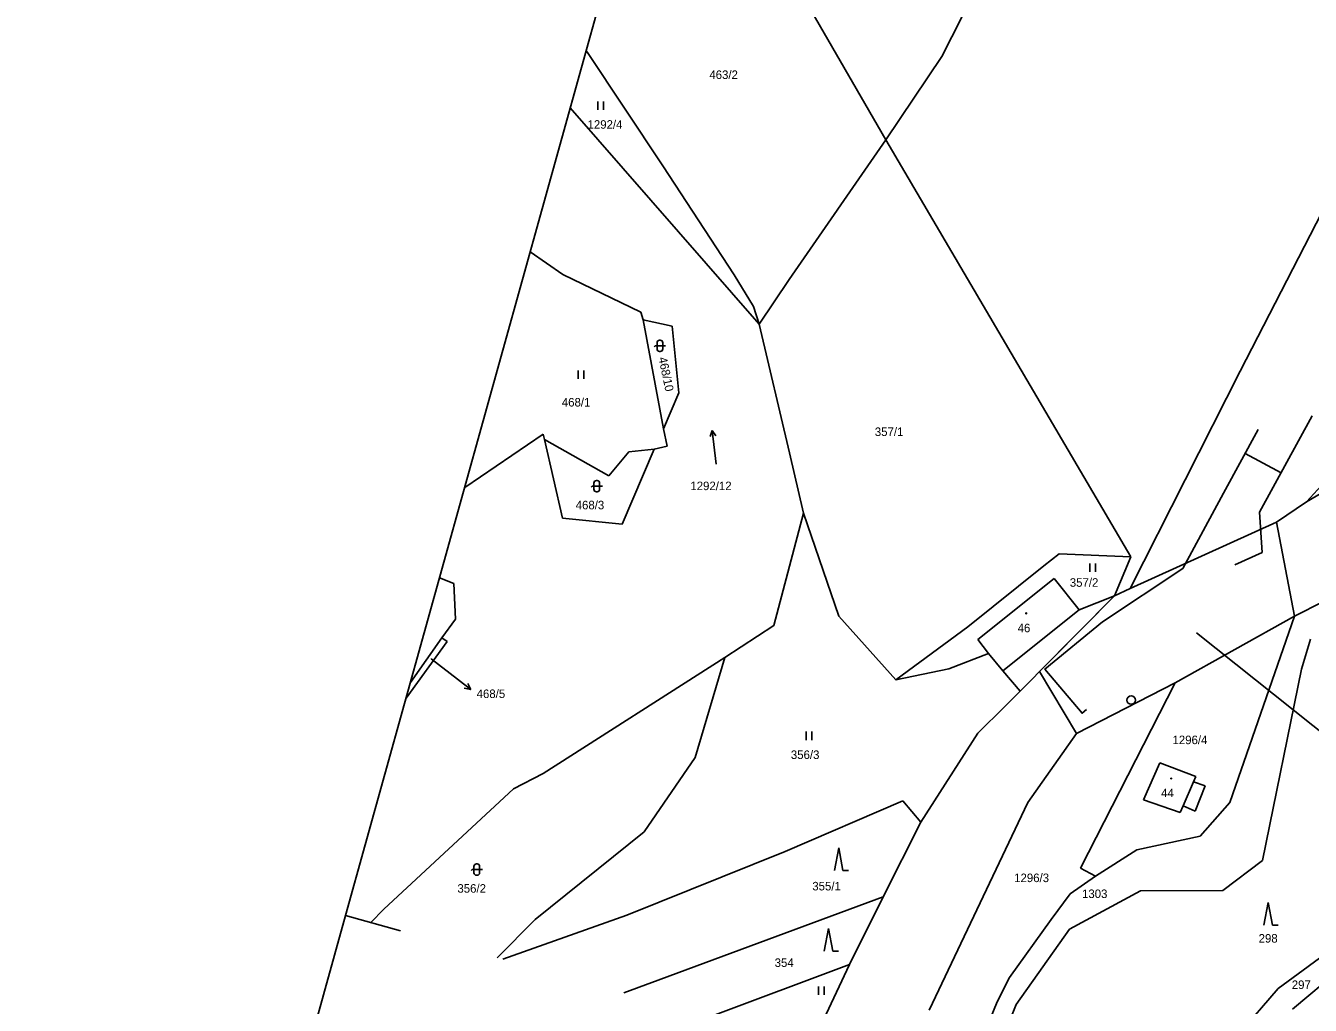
# Model space of a CAD drawing. Extents: x -795094 to -794639, y -1135368 to -1134681.
# Drawn here: x -795094.1 to -794868.2, y -1135101.6 to -1134929.4 of the extents above; entities that cross this region are included whole.
import ezdxf

# ---------------------------------------------------------------- set-up
doc = ezdxf.new("R2010")
doc.units = 0
for name, color, linetype in [('Default', 7, 'Continuous'), ('formát', 7, 'Continuous'), ('kilometráž - vrstava 7', 7, 'Continuous'), ('kn_celek - Cisla parcel pomocna', 7, 'Continuous'), ('kn_celek - Cisla pozemkovych parcel', 7, 'Continuous'), ('kn_celek - Cisla stavebnich parcel', 7, 'Continuous'), ('kn_celek - Hranice parcel', 7, 'Continuous'), ('kn_celek - Vnitrni kresby', 7, 'Continuous'), ('kn_celek - Znacky budov', 7, 'Continuous'), ('kn_celek - Znacky kultur', 7, 'Continuous'), ('plochy - SZDC', 7, 'Continuous'), ('plochy - TZ_ostat', 7, 'Continuous'), ('PSR_C2_1_trasa_Strunkovice - Kabelová trasa', 7, 'Continuous'), ('SOPS', 7, 'Continuous')]:
    doc.layers.add(name, color=color, linetype=linetype)

# ---------------------------------------------------------------- blocks, each defined once
blk = doc.blocks.new('308')
at = {"layer": 'Default'}
for p, q in [((-7.5, 0.2), (0, 40.2)), ((0, 40.2), (7.5, 0.2)), ((7.5, 0.2), (17.5, 0.2))]:
    blk.add_line(p, q, dxfattribs=at)
blk = doc.blocks.new('306')
at = {"layer": 'Default'}
for p, q in [((-5.2, 0), (-5.2, 15)), ((4.8, 0), (4.8, 15))]:
    blk.add_line(p, q, dxfattribs=at)
blk = doc.blocks.new('316')
at = {"layer": 'Default'}
for p, q in [((-8.3, 10), (-10, 8.1)), ((-5, 10), (-8.3, 10)), ((-5, 15.5), (-5, 4.5)), ((-5, 10), (5, 10)), ((0.5, 20), (-0.5, 20)), ((-0.5, 0), (0.5, 0)), ((5, 4.5), (5, 15.5)), ((10, 10), (5, 10))]:
    blk.add_line(p, q, dxfattribs=at)
for centre, start, end in [((-0.5, 15.5), 90, 180), ((-0.5, 4.5), 180, 270), ((0.5, 15.5), 0, 90), ((0.5, 4.5), 270, 0)]:
    blk.add_arc(centre, 4.5, start, end, dxfattribs=at)
blk = doc.blocks.new('802')
at = {"layer": 'Default'}
for p, q in [((-30, 0), (30, 0)), ((20, 5), (30, 0)), ((30, 0), (20, -5))]:
    blk.add_line(p, q, dxfattribs=at)
blk = doc.blocks.new('402')
at = {"layer": 'Default'}
for p, q in [((-0.8, 0.8), (0.7, 0.8)), ((-0.8, 0.8), (-0.8, -0.7)), ((0.7, 0.8), (0.7, -0.7)), ((0.7, -0.7), (-0.8, -0.7))]:
    blk.add_line(p, q, dxfattribs=at)
blk = doc.blocks.new('Z61')
at = {"layer": 'Default'}
for p, q in [((0, 0), (30, 0)), ((30, 0), (19.2, 5.3)), ((30, 0), (19.2, -5.3))]:
    blk.add_line(p, q, dxfattribs=at)

msp = doc.modelspace()

# ---------------------------------------------------------------- linework, layer by layer
at = {"layer": 'formát'}
for p, q in [((-794981.56, -1134883.54), (-795037.81, -1135085.87)), ((-795037.81, -1135085.87), (-795094.06, -1135288.19)), ((-795037.81, -1135085.87), (-795028.18, -1135088.55))]:
    msp.add_line(p, q, dxfattribs=at)
at = {"layer": 'kilometráž - vrstava 7'}
msp.add_circle((-794899.69, -1135047.96), 0.75, dxfattribs=at)
at = {"layer": 'kn_celek - Cisla parcel pomocna'}
msp.add_line((-795022.79, -1135040.69), (-795018.15, -1135044.27), dxfattribs=at)
at = {"layer": 'kn_celek - Hranice parcel'}
for p, q in [((-794896.43, -1134862.72), (-794933, -1134934.78)), ((-794942.82, -1134949.44), (-794981.32, -1134882.7)), ((-794995.38, -1134933.92), (-794995.55, -1134933.86)), ((-794995.38, -1134933.92), (-794982.02, -1134954.03)), ((-794933, -1134934.78), (-794942.82, -1134949.44)), ((-794998.32, -1134943.84), (-794965.12, -1134981.87)), ((-794942.82, -1134949.44), (-794959.81, -1134973.99)), ((-794942.82, -1134949.44), (-794899.77, -1135022.77)), ((-794880.53, -1134990.11), (-794861.46, -1134953)), ((-794982.02, -1134954.03), (-794969.49, -1134973.19)), ((-794999.6, -1134973.14), (-795005.36, -1134969.13)), ((-794985.93, -1134979.73), (-794999.6, -1134973.14)), ((-794969.49, -1134973.19), (-794966.1, -1134978.78)), ((-794959.81, -1134973.99), (-794965.12, -1134981.87)), ((-794966.1, -1134978.78), (-794965.12, -1134981.87)), ((-794985.48, -1134981.11), (-794985.93, -1134979.73)), ((-794980.42, -1134982.24), (-794985.48, -1134981.11)), ((-794985.48, -1134981.11), (-794981.95, -1135000.26)), ((-794979.23, -1134993.91), (-794980.42, -1134982.24)), ((-794959.79, -1135004.49), (-794965.12, -1134981.87)), ((-794899.86, -1135028.32), (-794880.53, -1134990.11)), ((-794981.95, -1135000.26), (-794979.23, -1134993.91)), ((-794868.85, -1135013.13), (-794854.54, -1134997.31)), ((-795016.88, -1135010.58), (-795003.06, -1135001.2)), ((-795002.85, -1135002.14), (-795003.06, -1135001.2)), ((-794981.27, -1135003.34), (-794981.95, -1135000.26)), ((-794868.85, -1135013.13), (-794849.21, -1135001.34)), ((-794991.53, -1135008.54), (-795002.85, -1135002.14)), ((-794999.7, -1135015.95), (-795002.85, -1135002.14)), ((-794983.54, -1135003.83), (-794981.27, -1135003.34)), ((-794991.53, -1135008.54), (-794988.03, -1135004.32)), ((-794983.54, -1135003.83), (-794989.19, -1135017.05)), ((-794988.03, -1135004.32), (-794983.54, -1135003.83)), ((-794957.31, -1135015.09), (-794959.79, -1135004.49)), ((-794874.12, -1135016.68), (-794868.85, -1135013.13)), ((-794989.19, -1135017.05), (-794999.7, -1135015.95)), ((-794957.31, -1135015.09), (-794962.5, -1135034.84)), ((-794951.09, -1135033.23), (-794957.31, -1135015.09)), ((-794899.86, -1135028.32), (-794874.12, -1135016.68)), ((-794912.38, -1135022.22), (-794915.04, -1135024.35)), ((-794899.77, -1135022.77), (-794912.38, -1135022.22)), ((-794902.64, -1135029.63), (-794899.77, -1135022.77)), ((-794915.04, -1135024.35), (-794928.44, -1135035.1)), ((-795021.3, -1135026.49), (-795018.76, -1135027.47)), ((-795018.76, -1135027.47), (-795018.5, -1135033.72)), ((-794913.25, -1135026.58), (-794926.65, -1135037.33)), ((-794908.85, -1135032.1), (-794913.25, -1135026.58)), ((-794902.64, -1135029.63), (-794899.86, -1135028.32)), ((-794919.2, -1135046.42), (-794902.64, -1135029.63)), ((-794908.85, -1135032.1), (-794902.64, -1135029.63)), ((-794871, -1135033.19), (-794865.9, -1135030.62)), ((-795018.5, -1135033.72), (-795020.87, -1135037.03)), ((-794962.5, -1135034.84), (-794971.13, -1135040.48)), ((-794941.08, -1135044.38), (-794951.09, -1135033.23)), ((-794928.44, -1135035.1), (-794941.08, -1135044.38)), ((-794891.95, -1135044.96), (-794871, -1135033.19)), ((-794882.37, -1135065.96), (-794871, -1135033.19)), ((-795026.42, -1135044.9), (-795020.87, -1135037.03)), ((-795020.87, -1135037.03), (-795019.96, -1135037.66)), ((-794926.65, -1135037.33), (-794924.8, -1135039.76)), ((-794868.19, -1135037.26), (-794869.73, -1135042.52)), ((-795019.96, -1135037.66), (-795027.18, -1135047.62)), ((-794931.78, -1135042.48), (-794924.8, -1135039.76)), ((-794924.8, -1135039.76), (-794922.28, -1135042.81)), ((-795003.08, -1135060.87), (-794971.13, -1135040.48)), ((-794971.13, -1135040.48), (-794976.36, -1135058.04)), ((-794941.08, -1135044.38), (-794931.78, -1135042.48)), ((-794922.28, -1135042.81), (-794919.2, -1135046.42)), ((-794869.73, -1135042.52), (-794876.61, -1135076.18)), ((-794921.91, -1135049.12), (-794919.2, -1135046.42)), ((-794926.68, -1135053.76), (-794921.91, -1135049.12)), ((-794936.68, -1135069.45), (-794926.68, -1135053.76)), ((-794976.36, -1135058.04), (-794985.34, -1135071.11)), ((-794894.67, -1135059.02), (-794897.53, -1135065.5)), ((-794888.34, -1135061.42), (-794894.67, -1135059.02)), ((-795008.32, -1135063.58), (-795003.08, -1135060.87)), ((-794888.72, -1135062.37), (-794888.34, -1135061.42)), ((-794886.66, -1135063.05), (-794888.72, -1135062.37)), ((-795031.08, -1135084.71), (-795008.32, -1135063.58)), ((-794888.42, -1135067.48), (-794886.66, -1135063.05)), ((-794960.56, -1135074.59), (-794939.83, -1135065.68)), ((-794939.83, -1135065.68), (-794936.68, -1135069.45)), ((-794897.53, -1135065.5), (-794891.09, -1135067.74)), ((-794891.09, -1135067.74), (-794890.55, -1135066.56)), ((-794890.55, -1135066.56), (-794888.42, -1135067.48)), ((-794887.59, -1135071.89), (-794882.37, -1135065.96)), ((-794985.34, -1135071.11), (-795004.51, -1135086.57)), ((-794943.32, -1135082.54), (-794936.68, -1135069.45)), ((-794898.7, -1135074.32), (-794887.59, -1135071.89)), ((-794988.38, -1135085.79), (-794960.56, -1135074.59)), ((-794905.97, -1135078.95), (-794898.7, -1135074.32)), ((-794871.31, -1135102.33), (-794839.63, -1135075.55)), ((-794876.61, -1135076.18), (-794883.58, -1135081.44)), ((-794873.86, -1135098.71), (-794845.43, -1135077.77)), ((-794983.97, -1135097.61), (-794943.32, -1135082.54)), ((-794949.24, -1135094.46), (-794943.32, -1135082.54)), ((-794898.07, -1135081.51), (-794910.52, -1135088.23)), ((-794883.58, -1135081.44), (-794898.07, -1135081.51)), ((-795033.41, -1135087.09), (-795031.08, -1135084.71)), ((-795004.51, -1135086.57), (-795011.14, -1135093.28)), ((-795010.15, -1135093.56), (-794988.38, -1135085.79)), ((-794910.52, -1135088.23), (-794919.92, -1135101.5)), ((-794973.79, -1135103.67), (-794949.24, -1135094.46)), ((-794953.8, -1135104.19), (-794949.24, -1135094.46)), ((-794988.91, -1135099.46), (-794983.97, -1135097.61)), ((-794890.58, -1135118.02), (-794873.86, -1135098.71)), ((-794919.92, -1135101.5), (-794922.71, -1135108.46))]:
    msp.add_line(p, q, dxfattribs=at)
at = {"layer": 'kn_celek - Vnitrni kresby'}
for p, q in [((-794922.28, -1135042.81), (-794908.85, -1135032.1)), ((-794888.72, -1135062.37), (-794890.55, -1135066.56))]:
    msp.add_line(p, q, dxfattribs=at)
at = {"layer": 'plochy - SZDC'}
for p, q in [((-794861.46, -1134953), (-794880.53, -1134990.11)), ((-794880.53, -1134990.11), (-794899.86, -1135028.32)), ((-794868.85, -1135013.13), (-794854.54, -1134997.31)), ((-794874.12, -1135016.68), (-794868.85, -1135013.13)), ((-794899.86, -1135028.32), (-794874.12, -1135016.68)), ((-794891.95, -1135044.96), (-794909.29, -1135053.85)), ((-794908.62, -1135077.55), (-794891.95, -1135044.96)), ((-794909.29, -1135053.85), (-794917.84, -1135065.96)), ((-794917.84, -1135065.96), (-794935.22, -1135102.48)), ((-794905.97, -1135078.95), (-794908.62, -1135077.55)), ((-794910.45, -1135082.04), (-794905.97, -1135078.95)), ((-794913.75, -1135086.58), (-794910.45, -1135082.04)), ((-794921.11, -1135096.78), (-794913.75, -1135086.58)), ((-794923.26, -1135101.03), (-794921.11, -1135096.78)), ((-794929.35, -1135116.02), (-794923.26, -1135101.03))]:
    msp.add_line(p, q, dxfattribs=at)
at = {"layer": 'plochy - TZ_ostat'}
for p, q in [((-794874.12, -1135016.68), (-794899.86, -1135028.32)), ((-794871, -1135033.19), (-794874.12, -1135016.68)), ((-794871, -1135033.19), (-794874.12, -1135016.68)), ((-794899.86, -1135028.32), (-794902.64, -1135029.63)), ((-794902.64, -1135029.63), (-794915.79, -1135042.96)), ((-794891.95, -1135044.96), (-794871, -1135033.19)), ((-794915.79, -1135042.96), (-794909.29, -1135053.85)), ((-794915.79, -1135042.96), (-794909.29, -1135053.85)), ((-794909.29, -1135053.85), (-794891.95, -1135044.96))]:
    msp.add_line(p, q, dxfattribs=at)
at = {"layer": 'PSR_C2_1_trasa_Strunkovice - Kabelová trasa'}
for p, q in [((-794867.89, -1134997.98), (-794877.13, -1135014.95)), ((-794877.35, -1135000.36), (-794883.44, -1135011.57)), ((-794883.44, -1135011.57), (-794890.6, -1135024.81)), ((-794890.6, -1135024.81), (-794904.75, -1135034.23))]:
    msp.add_line(p, q, dxfattribs=at)
for points in [[(-794873.34, -1135007.99), (-794879.66, -1135004.61)], [(-794881.49, -1135024.17), (-794876.67, -1135022.01), (-794877.13, -1135014.95)], [(-794907.55, -1135049.65), (-794908.33, -1135050.29), (-794914.86, -1135042.51), (-794904.75, -1135034.23)]]:
    msp.add_lwpolyline(points, dxfattribs=at)
at = {"layer": 'SOPS'}
msp.add_line((-794888.21, -1135036.13), (-794864.32, -1135055.18), dxfattribs=at)

# ---------------------------------------------------------------- block references
at = {"layer": 'kn_celek - Cisla parcel pomocna', "xscale": 0.1, "yscale": 0.10000000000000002, "rotation": -37.71054000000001}
msp.add_blockref('Z61', (-795018.15, -1135044.27), dxfattribs=at)
at = {"layer": 'kn_celek - Znacky budov', "xscale": 0.1, "yscale": 0.10000000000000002}
for p in [(-794918.16, -1135032.73), (-794892.67, -1135061.76)]:
    msp.add_blockref('402', p, dxfattribs=at)
at = {"layer": 'kn_celek - Znacky kultur', "xscale": 0.1, "yscale": 0.10000000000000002}
for name, p in [('306', (-794992.93, -1134944.19)), ('316', (-794982.55, -1134986.67)), ('306', (-794996.42, -1134991.48)), ('316', (-794993.66, -1135011.35)), ('306', (-794906.47, -1135025.43)), ('306', (-794956.32, -1135055)), ('308', (-794951.12, -1135077.96)), ('316', (-795014.75, -1135078.77)), ('308', (-794875.6, -1135087.6)), ('308', (-794952.91, -1135092.17)), ('306', (-794954.14, -1135099.83))]:
    msp.add_blockref(name, p, dxfattribs=at)
at = {"layer": 'kn_celek - Znacky kultur', "xscale": 0.09999999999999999, "yscale": 0.10000000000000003, "rotation": 96.3558}
msp.add_blockref('802', (-794973.01, -1135003.52), dxfattribs=at)

# ---------------------------------------------------------------- texts
at = {"layer": 'kn_celek - Cisla parcel pomocna'}
msp.add_text('468/5', height=1.5, dxfattribs=at).set_placement((-795014.78, -1135047.61))
at = {"layer": 'kn_celek - Cisla pozemkovych parcel'}
for s, height, p in [('463/2', 1.5, (-794973.86, -1134938.74)), ('1292/4', 1.5, (-794995.28, -1134947.49)), ('468/1', 1.5, (-794999.8, -1134996.34)), ('357/1', 1.5, (-794944.77, -1135001.53)), ('1292/12', 1.5, (-794977.2, -1135011.05)), ('468/3', 1.5, (-794997.36, -1135014.42)), ('357/2', 1.5, (-794910.49, -1135028.04)), ('468/5', 0.1, (-795023.02, -1135040.66)), ('1296/4', 1.5, (-794892.43, -1135055.72)), ('356/3', 1.5, (-794959.53, -1135058.33)), ('356/2', 1.5, (-795018.16, -1135081.84)), ('355/1', 1.5, (-794955.76, -1135081.44)), ('1296/3', 1.5, (-794920.27, -1135079.98)), ('1303', 1.5, (-794908.34, -1135082.78)), ('298', 1.5, (-794877.29, -1135090.62)), ('354', 1.5, (-794962.38, -1135094.9)), ('297', 1.5, (-794871.46, -1135098.78))]:
    msp.add_text(s, height=height, dxfattribs=at).set_placement(p)
msp.add_text('468/10', height=1.5, rotation=281.8751, dxfattribs=at).set_placement((-794982.82, -1134987.8))
at = {"layer": 'kn_celek - Cisla stavebnich parcel'}
for s, p in [('46', (-794919.66, -1135036.04)), ('44', (-794894.42, -1135065.04))]:
    msp.add_text(s, height=1.5, dxfattribs=at).set_placement(p)

doc.saveas('drawing.dxf')
